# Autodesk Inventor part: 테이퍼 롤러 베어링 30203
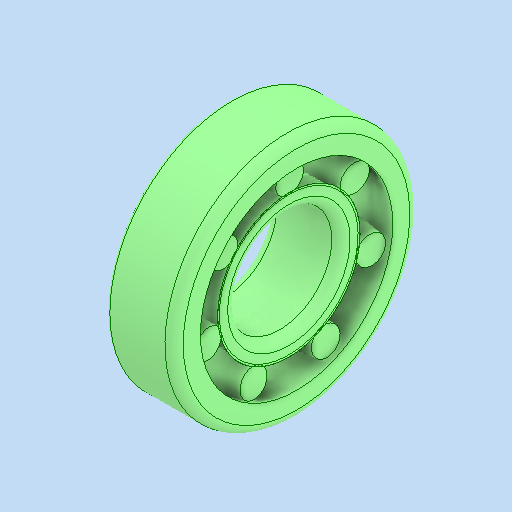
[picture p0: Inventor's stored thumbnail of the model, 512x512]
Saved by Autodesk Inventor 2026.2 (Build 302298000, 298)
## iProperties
Created: 2026-01
Part Number: 테이퍼 롤러 베어링 30203
Material: 강철, 연강
Description: 테이퍼 롤러 베어링
Document SubType Name: Modeling
Designer: PC2-07
Density: 7.85 g/cm^3
Appearance: 기본값
Author: jhkim
Sending System: Autodesk Inventor 2026
Preprocessor: ST-DEVELOPER v20.1
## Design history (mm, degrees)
feature "Solid1"
feature "Solid1:1"
node "솔리드1"
node "솔리드2"
